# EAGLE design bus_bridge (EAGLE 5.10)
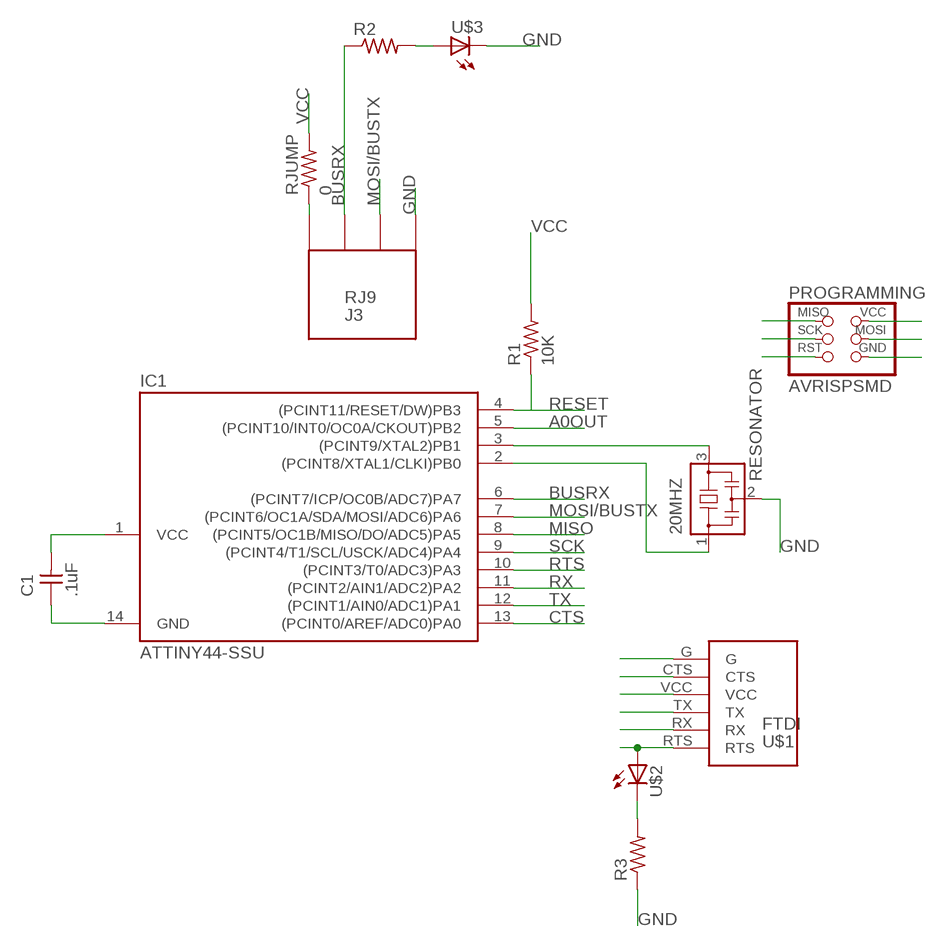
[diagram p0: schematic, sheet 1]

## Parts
20MHZ  RESONATOR  [EFOBM]
C1  .1uF  UNPOLARIZED_CAPACITOR1206  [1206]
IC1  ATTINY44-SSU  [SOIC14]
J3  RJ9  [RJ9_SMD]
PROGRAMMING  AVRISPSMD  [2X03SMD]
R1  10K  RESISTOR1206  [1206]
R2  RESISTOR1206  [1206]
R3  RESISTOR1206  [1206]
RJUMP  0  RESISTOR1206  [1206]
U$1  FTDI  [FTDI_SMD]
U$2  LED1206  [1206]
U$3  LED1206  [1206]

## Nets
A0OUT: IC1.5((PCINT10/INT0/OC0A/CKOUT)PB2)
BUSRX: IC1.6((PCINT7/ICP/OC0B/ADC7)PA7) J3.2 R2.1
CTS: IC1.13((PCINT0/AREF/ADC0)PA0) U$1.CTS
GND: 20MHZ.2 C1.1 IC1.14(GND) J3.4 PROGRAMMING.6(GND) R3.1 U$1.G U$3.2(C)
MISO: IC1.8((PCINT5/OC1B/MISO/DO/ADC5)PA5) PROGRAMMING.1(MISO)
MOSI/BUSTX: IC1.7((PCINT6/OC1A/SDA/MOSI/ADC6)PA6) J3.3 PROGRAMMING.4(MOSI)
N$1: 20MHZ.3 IC1.3((PCINT9/XTAL2)PB1)
N$2: 20MHZ.1 IC1.2((PCINT8/XTAL1/CLKI)PB0)
N$3: J3.1 RJUMP.1
N$4: R3.2 U$2.2(C)
N$5: R2.2 U$3.1(A)
RESET: IC1.4((PCINT11/RESET/DW)PB3) PROGRAMMING.5(RST) R1.1
RTS: IC1.10((PCINT3/T0/ADC3)PA3) U$1.RTS U$2.1(A)
RX: IC1.11((PCINT2/AIN1/ADC2)PA2) U$1.RX
SCK: IC1.9((PCINT4/T1/SCL/USCK/ADC4)PA4) PROGRAMMING.3(SCK)
TX: IC1.12((PCINT1/AIN0/ADC1)PA1) U$1.TX
VCC: C1.2 IC1.1(VCC) PROGRAMMING.2(VCC) R1.2 RJUMP.2 U$1.VCC

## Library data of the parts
20MHZ = fab:RESONATOR
C1 = ng:UNPOLARIZED_CAPACITOR: unpolarized_capacitor
IC1 = fab:ATTINY44
J3 = nadya:RJ9
PROGRAMMING = fab:AVRISP
R1-R3 RJUMP = ng:RESISTOR
U$1 = nadya:FTDI: Header pads for FTDI SMD header. Plug in flat FTDI cable on f-type smd header.
U$2 U$3 = ng:LED

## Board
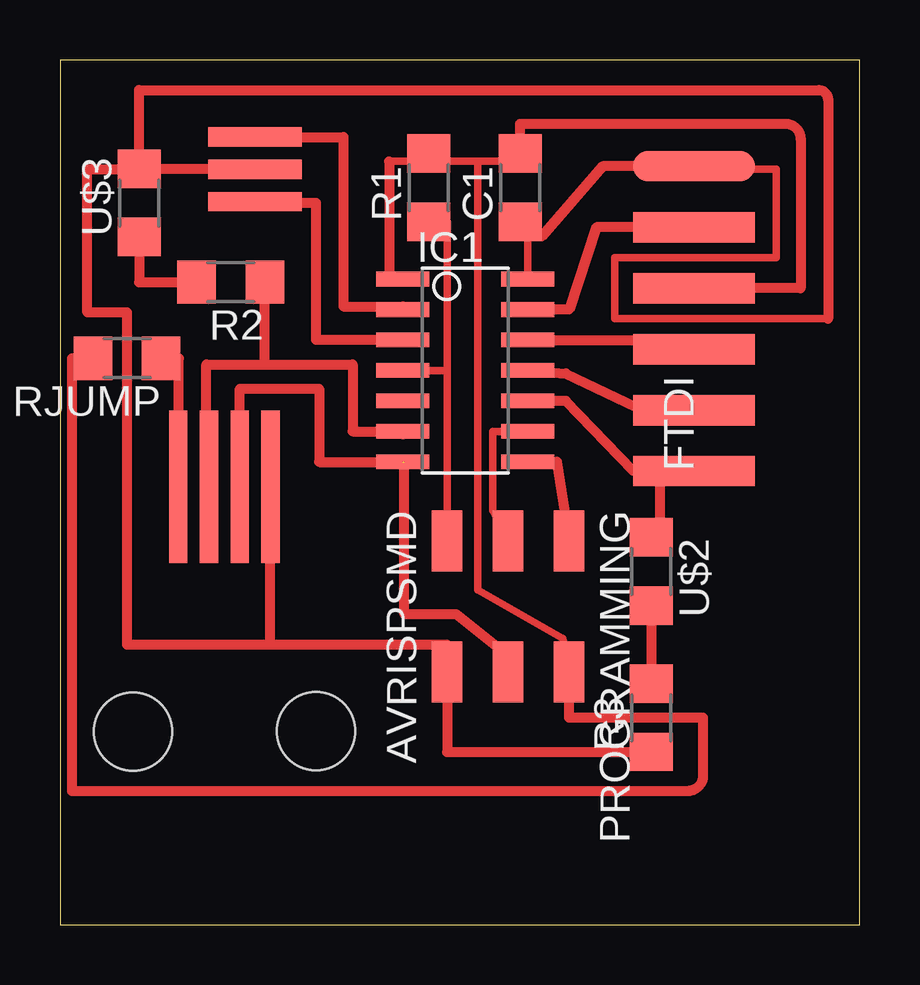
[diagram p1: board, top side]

Size 33.33 x 36.06 mm. Coordinates in mm from the lower left corner, seen from the top.
Outline: 0,0 33.33,0 33.33,36.06 0,36.06 0,0
Copper layers (1*16): Top 0.035mm / dielectric 1.5mm / Bottom 0.035mm
Design rules "default": minimum track width 10mil, minimum drill 24mil, track to track 8mil, track to pad 8mil, pad to pad 8mil, via to via 8mil, smd to smd 8mil, copper to edge 40mil, drill to drill 8mil, minimum pad ring 10mil, minimum via ring 8mil, stop-mask expansion 4mil, vias tented up to drill 0mil, thermal gap 10mil

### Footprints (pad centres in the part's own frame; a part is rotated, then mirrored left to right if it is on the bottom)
EFOBM = smd 0.8 x 3.9: 1 -1.35,0; 2 0,0; 3 1.35,0
1206 = smd 1.6 x 1.803: 1 -1.422,0; 2 1.422,0
SOIC14 = smd 0.61 x 2.21: 1 -3.81,-2.603; 2 -2.54,-2.603; 3 -1.27,-2.603; 4 0,-2.603; 5 1.27,-2.603; 6 2.54,-2.603; 7 3.81,-2.603; 8 3.81,2.603; 9 2.54,2.603; 10 1.27,2.603; 11 0,2.603; 12 -1.27,2.603; 13 -2.54,2.603; 14 -3.81,2.603
RJ9_SMD = smd 0.76 x 6.35: 1 -1.93,3.16; 2 -0.65,3.16; 3 0.63,3.16; 4 1.91,3.16 | hole 3.25: -3.81,-7.05; 3.81,-7.03
2X03SMD = smd 2.54 x 1.27: 1 -2.54,2.54; 2 2.92,2.54; 3 -2.54,0; 4 2.92,0; 5 -2.54,-2.54; 6 2.92,-2.54
FTDI_SMD = smd 5.08 x 1.27: CTS 0,2.54; G 0,5.08; RTS 0,-7.62; RX 0,-5.08; TX 0,-2.54; VCC 0,0

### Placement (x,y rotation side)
20MHZ  8.13,31.5 270 top
C1  19.18,30.73 90 top
IC1  16.89,23.11 270 top
J3  6.86,15.11 0 top
PROGRAMMING  18.67,13.46 270 top
R1  15.37,30.73 90 top
R2  7.11,26.8 180 top
R3  24.64,8.64 90 top
RJUMP  2.79,23.62 180 top
U$1  26.42,26.54 0 top
U$2  24.64,14.73 270 top
U$3  3.3,30.1 90 top

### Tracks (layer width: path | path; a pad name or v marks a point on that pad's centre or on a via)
BUSRX
  Top 0.406: 14.29,20.45 IC1.6 12.19,20.57 12.19,23.37 8.53,23.37 | J3.2 6.1,18.27 6.1,23.37 8.53,23.37 | 8.53,23.37 R2.1
CTS
  Top 0.406: U$1.CTS 22.35,29.08 21.21,25.65 IC1.13
GND
  Top 0.305: C1.1 19.49,29.31 IC1.14 | 32,25.27 23.11,25.27 23.11,27.81 29.84,27.81 29.84,31.5 26.42,31.5 U$1.G
  Top 0.406: U$1.G 22.61,31.62 20.07,28.7 C1.1 | 32,25.27 32,34.42 arc90 31.62,34.8 3.3,34.8 U$3.2 | R3.1 16.13,7.21 PROGRAMMING.6 16.13,11.68 8.76,11.68 | U$3.2 8.13,31.52 20MHZ.2 | J3.4 8.76,18.02 8.76,11.68 | 8.76,11.68 2.79,11.68 2.79,25.53 1.14,25.53 1.14,31.5 3.3,31.5 U$3.2
MISO
  Top 0.406: IC1.8 20.7,19.3 PROGRAMMING.1
MOSI/BUSTX  (1 unrouted)
  Top 0.406: PROGRAMMING.4 18.29,11.56 16.51,12.95 14.35,12.95 14.35,19.3 | J3.3 7.49,18.02 7.49,22.35 10.79,22.35 10.79,19.3 IC1.7
N$1
  Top 0.406: IC1.3 10.67,24.38 10.67,30.1 8.13,30.1 20MHZ.3
N$2
  Top 0.406: 20MHZ.1 11.81,32.85 11.81,25.78 14.29,25.78 IC1.2
N$3
  Top 0.406: RJUMP.1 4.95,23.62 4.95,19.81 5.05,20.57 J3.1
N$4
  Top 0.406: U$2.2 R3.2
N$5
  Top 0.406: U$3.1 3.3,26.8 R2.2
RESET
  Top 0.305: R1.1 16.13,29.31 16.13,23.11 | 16.13,23.11 IC1.4 | PROGRAMMING.5 16.13,23.11
RTS
  Top 0.406: 25.02,18.92 23.88,18.92 21.08,21.84 IC1.10 | 25.02,18.92 U$1.RTS | U$2.1 25.02,16.15 25.02,18.92
RX
  Top 0.406: U$1.RX 24,21.59 21.08,22.99 IC1.11
SCK
  Top 0.305: PROGRAMMING.3 18.03,17.27 18.03,20.57 IC1.9
TX
  Top 0.406: U$1.TX 25.27,24 25.27,24.38 IC1.12
VCC
  Top 0.305: 21.46,10.67 PROGRAMMING.2 20.95,11.94 17.4,13.97 17.4,31.83 | 16.13,31.83 13.72,31.83 | 16.13,31.83 R1.2 | 17.4,31.83 18.92,31.83 C1.2 | 17.4,31.83 16.13,31.83
  Top 0.406: IC1.1 13.72,26.92 13.72,31.83 | U$1.VCC 30.86,26.54 30.86,32.77 arc90 30.23,33.4 19.18,33.4 C1.2 | PROGRAMMING.2 21.21,8.64 26.8,8.64 26.8,6.22 arc-90 26.16,5.59 0.51,5.59 0.51,23.62 RJUMP.2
